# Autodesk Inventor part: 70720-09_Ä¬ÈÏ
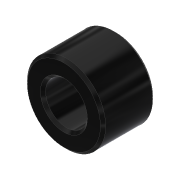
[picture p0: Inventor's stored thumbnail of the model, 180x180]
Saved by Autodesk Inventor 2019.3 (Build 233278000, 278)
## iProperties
Created: 2010-06
Part Number: 70720-09_Ä¬ÈÏ
Material: Ogólny
Document SubType Name: Modeling
Designer: CADENGINEERING4
Density: 1 g/cm^3
Appearance: Gładki — czarny
Author: CADENGINEERING4
Revision Number: ÈÎºÎ
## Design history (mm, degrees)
feature "NONE"
node "Bryła1"
